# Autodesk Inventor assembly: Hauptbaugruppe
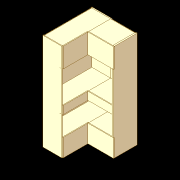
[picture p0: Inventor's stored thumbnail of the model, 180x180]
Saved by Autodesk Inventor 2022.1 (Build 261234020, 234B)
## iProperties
Created: 2022-07
Part Number: Hauptbaugruppe
Document SubType Name: Assembly
Designer: Ruhl
Author: Ruhl
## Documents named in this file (3)
- Z:\INVENTOR\FORUM UND TEST\VOLUMENKÖRPER VERSCHMELZEN\Hauptbaugruppe.iam
- Z:\INVENTOR\FORUM UND TEST\VOLUMENKÖRPER VERSCHMELZEN\Schrank-5.iam
- Z:\INVENTOR\FORUM UND TEST\VOLUMENKÖRPER VERSCHMELZEN\Schrank-6.iam
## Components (2 placed, 2 different names)
1. Schrank-5:1 [sub-assembly] — Passend:1, Fluchtend:1, Fluchtend:2
2. Schrank-6:1 [sub-assembly] — Passend:1, Fluchtend:1, Fluchtend:2
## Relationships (3: Flush 2, Mate 1)
- Passend:1 [Mate]: Schrank-5:1 ↔ Schrank-6:1
- Fluchtend:1 [Flush]: Schrank-5:1 ↔ Schrank-6:1
- Fluchtend:2 [Flush]: Schrank-5:1 ↔ Schrank-6:1
